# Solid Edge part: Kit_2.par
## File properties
Author: ahadarics
Last saved by: ahadarics
Revision: 82
Sűrűség: 0,000 kg/m^3
Pontosság: 0,990
Username: ahadarics
Dokumentum tartalom típus: 0
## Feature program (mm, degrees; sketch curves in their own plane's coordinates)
base feature "unnamed BaseFeature 1"
sketch for "Furat_2" plane through (0, 3.5, 12) normal (0, 0, 1) x-axis (0, 1, 0)
hole "Furat_2" diameter 9.728 finite  ThreadDepth = 7.5 mm
sketch for "Kihúzás_1" #1 plane through (0, 31.25, 0) normal (0, 1, 0) x-axis (0, 0, -1)
sketch for "Kihúzás_1" #2 plane through (0, 31.25, 0) normal (0, 1, 0) x-axis (0, 0, -1)
  arc centre (0, 0) radius 11 from (7.5498, -8) to (-7.5498, -8) cw
extrude "Kihúzás_1" add finite 15.84 along -normal
thread "unnamed Thread 1"
chamfer "Letörés_1" setback 1.5
sketch for "Kivágás_2" #1 plane through (0, 31.25, 0) normal (0, 1, 0) x-axis (0, 0, -1)
  arc centre (0, 0) radius 11 from (7.5498, -8) to (-7.5498, -8) cw
  line (7.5498, -8) -> (-7.5498, -8)
sketch for "Kivágás_2" #2 plane through (0, 31.25, 0) normal (0, 1, 0) x-axis (0, 0, -1)
  line (-7.5498, 8) -> (7.5498, 8)
extrude "Kivágás_2" cut finite 15.84 along -normal
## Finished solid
Body 1: solid body, 55 faces, 114 edges, 66 vertices, 2 internal voids.
  Faces by surface: plane 22, cylinder 20, cone 12, spun 1
  Edges by curve: circle 48, line 48, intersection 9, spline 9
Bounding box of the edges (mm; curved faces can reach further): 26.800 x 37.500 x 25.400, from (-13.4, -6.25, -13.4) to (13.4, 31.25, 12).
Cylindrical faces by radius (mm): R0.875 x1, R1.7 x1, R1.75 x1, R3 x1, R4 x1, R4.28 x3, R4.283 x1, R5 x3, R9.85 x2, R11 x4, R11.1 x1, R13.4 x1
Conical faces (half-angle, radius in mm at the cone's reference point): 30 deg R1.8366 x1, 45 deg R1.55 x2, 45 deg R4.1 x2, 45 deg R4.28 x1, 45 deg R11 x2, 59 deg R1 x1, 59 deg R2.1415 x1, 60 deg R10.425 x2
Planar faces by outward normal: +x 2, +y 8, +z 6, -x 2, -y 3, -z 1
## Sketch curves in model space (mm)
arc centre (0, 31.25, 0) radius 11 from (-8, 31.25, 7.5498) through (-11, 31.25, 0) to (-8, 31.25, -7.5498)
line (-8, 31.25, 7.5498) -> (-8, 31.25, -7.5498)
arc centre (0, 31.25, 0) radius 11 from (8, 31.25, -7.5498) through (11, 31.25, 0) to (8, 31.25, 7.5498)
line (8, 31.25, -7.5498) -> (8, 31.25, 7.5498)
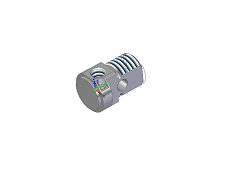
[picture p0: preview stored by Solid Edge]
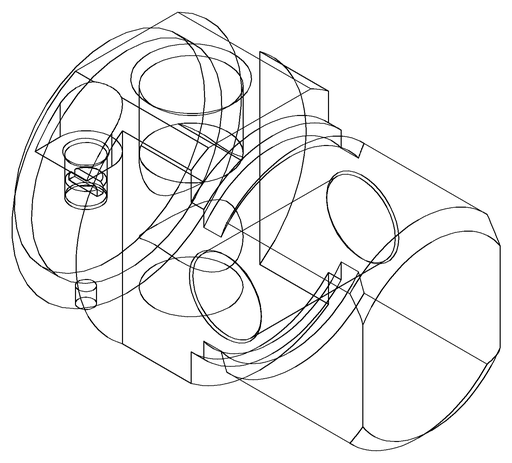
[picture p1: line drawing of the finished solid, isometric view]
